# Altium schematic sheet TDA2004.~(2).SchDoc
size A4
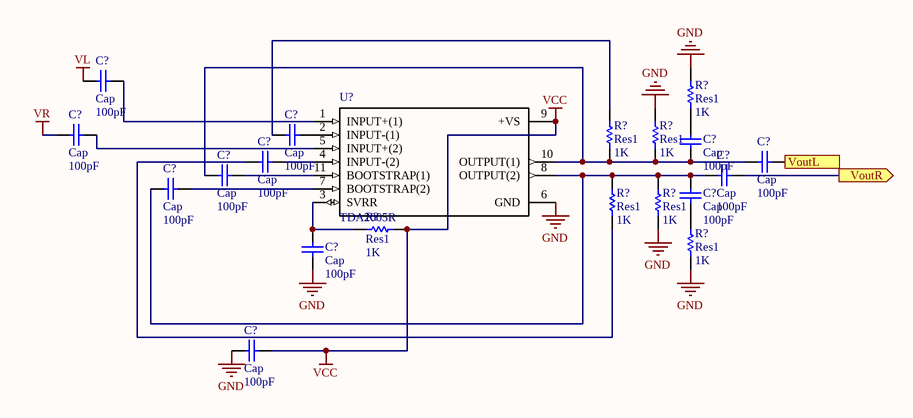
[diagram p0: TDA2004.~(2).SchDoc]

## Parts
(Parts that share a designator on the sheet are numbered #1, #2 ... from top to bottom, then left to right.)
C?#1  Cap  value 100pF  [RAD-0.3]
C?#2  Cap  value 100pF  [RAD-0.3]
C?#3  Cap  value 100pF  [RAD-0.3]
C?#4  Cap  value 100pF  [RAD-0.3]
C?#5  Cap  value 100pF  [RAD-0.3]
C?#6  Cap  value 100pF  [RAD-0.3]
C?#7  Cap  value 100pF  [RAD-0.3]
C?#8  Cap  value 100pF  [RAD-0.3]
C?#9  Cap  value 100pF  [RAD-0.3]
C?#10  Cap  value 100pF  [RAD-0.3]
C?#11  Cap  value 100pF  [RAD-0.3]
C?#12  Cap  value 100pF  [RAD-0.3]
R?#1  Res1  value 1K  [AXIAL-0.3]
R?#2  Res1  value 1K  [AXIAL-0.3]
R?#3  Res1  value 1K  [AXIAL-0.3]
R?#4  Res1  value 1K  [AXIAL-0.3]
R?#5  Res1  value 1K  [AXIAL-0.3]
R?#6  Res1  value 1K  [AXIAL-0.3]
R?#7  Res1  value 1K  [AXIAL-0.3]
U?  TDA2005R  [TO170P500X1990X2138-11P]

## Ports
VoutL (out), VoutR (out)

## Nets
GND: C?#11.1 C?#12.1 R?#1.2 R?#3.2 R?#6.1 R?#7.1 U?.6(GND)
VCC: C?#12.2 R?#4.2 U?.9(+VS)
VL: C?#1.1
VR: C?#2.1
VoutL: C?#6.2 ; port VoutL
VoutR: C?#8.2 ; port VoutR
NetC?#1_2: C?#1.2 U?.1(INPUT+(1))
NetC?#2_2: C?#2.2 U?.5(INPUT+(2))
NetC?#3_1: C?#3.1 R?#2.2
NetC?#3_2: C?#3.2 U?.2(INPUT-(1))
NetC?#4_1: C?#4.1 R?#5.1
NetC?#4_2: C?#4.2 U?.4(INPUT-(2))
NetC?#5_1: C?#5.1 C?#6.1 C?#7.1 R?#2.1 R?#3.1 U?.10(OUTPUT(1))
NetC?#5_2: C?#5.2 R?#1.1
NetC?#7_2: C?#7.2 U?.11(BOOTSTRAP(1))
NetC?#8_1: C?#8.1 C?#9.1 C?#10.2 R?#5.2 R?#6.2 U?.8(OUTPUT(2))
NetC?#9_2: C?#9.2 U?.7(BOOTSTRAP(2))
NetC?#10_1: C?#10.1 R?#7.2
NetC?#11_2: C?#11.2 R?#4.1 U?.3(SVRR)

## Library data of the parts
C?#1-C?#12 = Cap: Capacitor
R?#1-R?#7 = Res1: Resistor
U? = TDA2005R: Audio Amp Speaker 1-CH Mono/2-CH Stereo 22W Class-B Automotive 11-Pin_11+Tab_ MULTIWATT Tube; MF: STMicroelectronics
